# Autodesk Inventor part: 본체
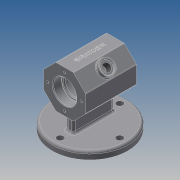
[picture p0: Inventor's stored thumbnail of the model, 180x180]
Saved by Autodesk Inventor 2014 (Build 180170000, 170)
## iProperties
Created: 2021-02
Part Number: 본체
Material: Generic
Document SubType Name: Modeling
Designer: kb542-17
Density: 1 g/cm^3
Appearance: Default
Author: kb542-17
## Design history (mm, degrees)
sketch "스케치1"
  geometry: C1 r 52 at (0, 0); C2 r 4.5 at (41, 0); C3 r 4.5 at (0, 41); C4 r 4.5 at (-41, 0); C5 r 4.5 at (0, -41); A1 r 41 centre (0, 0) between (41, 0) and (0, 41); 1 further point
  constraints: 6 centre point, 4 point on circle, 3 equal radius, 2 coincident, 2 horizontal alignment, 2 vertical alignment
  dimensions: "d0" = 104 diameter of C1; "d1" = 82 diameter of A1; "d2" = 9 diameter of C2
extrude "돌출1" new body sketch "스케치1" distance "d3" = 10; taper "d4" = 0 deg
sketch "스케치2" dims "d44" = 58
  geometry: L1 (12.012, 91)-(29, 74.012); L2 (29, 74.012)-(29, 49.988); L3 (29, 49.988)-(12.012, 33); L4 (12.012, 33)-(-12.012, 33); L5 (-12.012, 33)-(-29, 49.988); L6 (-29, 49.988)-(-29, 74.012); L7 (-29, 74.012)-(-12.012, 91); L8 (-12.012, 91)-(12.012, 91); 4 further points
  constraints: 16 end point, 2 vertical alignment, 1 coincident, 1 horizontal, 1 midpoint, 19 other
  dimensions: "d45" = 62 distance of point (0, 62) point (0, 0)
extrude "돌출2" join sketch "스케치2" stored distance "d7" = 70; taper "d8" = 0 deg
sketch "스케치7"
  geometry: L1 (-35, 74.012)-(-35, 49.988) reference; L2 (35, 49.988)-(35, 74.012) reference; L3 (-35, 62)-(35, 62); L4 (-35, 62)-(-35, 78); L5 (-35, 78)-(-23, 78); L6 (-23, 78)-(-23, 76); L7 (-23, 76)-(-20, 76); L8 (-20, 76)-(-20, 84); L9 (-20, 84)-(20, 84); L10 (20, 84)-(20, 76); L11 (20, 76)-(23, 76); L12 (23, 76)-(23, 78); L13 (23, 78)-(35, 78); L14 (35, 78)-(35, 62); 1 further point
  constraints: 24 end point, 6 perpendicular, 4 parallel, 2 midpoint, 1 collinear, 1 horizontal
  dimensions: "d55" = 44 diameter of L9 L3; "d56" = 28 diameter of L11 L3; "d57" = 32 diameter of L13 L3; "d58" = 28 diameter of L7 L3; "d59" = 32 diameter of L5 L3; "d60" = 12 distance of L4.end L5.end; "d61" = 3 distance of L6.end L7.end; "d62" = 40 distance of L8.end L9.end; "d63" = 12 distance of L12.end L13.end
revolve "회전2" sketch "스케치7" stored, may be unused: angle "d64" = 90 deg
sketch "스케치8"
  geometry: L1 (-5, -28)-(5, -28); L2 (5, -28)-(5, 28); L3 (5, 28)-(-5, 28); L4 (-5, 28)-(-5, -28); C1 r 52 at (0, 0) reference; 2 further points
  constraints: 8 end point, 2 midpoint, 2 parallel, 1 horizontal, 1 horizontal alignment, 1 perpendicular, 1 vertical alignment
  dimensions: "d65" = 10 distance between parallel lines of L2 L4; "d66" = 56 distance between parallel lines of L1 L3
extrude "돌출5" join sketch "스케치8" stored distance "d67" = 5; taper "d68" = 0 deg
sketch "스케치9"
  geometry: L1 (0, 0)-(-24.024, 0) reference; C1 r 10 at (-12.012, 35); 2 further points
  constraints: 1 centre point, 1 midpoint, 1 vertical alignment
  dimensions: "d69" = 20 diameter of C1; "d70" = 35 distance from line of L1 C1.centre
extrude "돌출6" join sketch "스케치9" distance "d71" = 5; taper "d72" = 0 deg
hole "구멍3" diameter "d75" = 10.917; stored, may be unused: countersink angle "d79" = 90 deg, drill point angle "d81" = 118 deg; dims "d73" = 10, "d74" = 10, "d76" = 8, "d77" = 16, "d78" = 2, "d80" = 10
sketch "스케치10" dims "d82" = 46
  geometry: C1 r 16 at (0, 62) reference; 3 further points
  constraints: 2 vertical alignment, 1 coincident, 2 other
hole "구멍4" sketch "스케치10" at (0, 85) diameter "d83" = 3.242; stored, may be unused: countersink angle "d87" = 90 deg, drill point angle "d89" = 118 deg; dims "d84" = 8, "d85" = 16, "d86" = 2, "d88" = 10
node "작업 평면1"
sketch "스케치11"
  geometry: L1 (24.024, -70)-(0, -70) reference; L2 (-16.988, 0)-(-16.988, -70) reference; 2 further points
  constraints: 1 other
  dimensions: "d94" = 35 distance from line of L1 point (12.012, -35); "d95" = 29 distance from line of L2 point (12.012, -35)
feature "엠보싱1" sketch "스케치11" dims "d96" = 0.5, "d97" = 0
fillet "모깎기1" dims "d98" = 1, "d99" = 0.3, "d100" = 3
fillet "모깎기2" dims "d101" = 3
chamfer "모따기1" distance "d102" = 1; stored, may be unused: second distance "d103" = 2, angle "d104" = 45 deg
node "솔리드1"
pattern_circular "원형 패턴1" dims angle "d91" = 360 deg
mirror "대칭1"
other parameters: "d93" = 23
